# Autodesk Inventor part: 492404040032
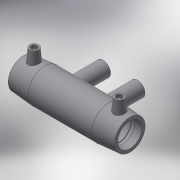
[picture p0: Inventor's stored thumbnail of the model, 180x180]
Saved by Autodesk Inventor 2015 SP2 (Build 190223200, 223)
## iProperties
Created: 2017-06
Part Number: 492404040032
Material: Generic
Description: PLASSON REDUCING TEE WITH TWO OUTLETS 40X32X32X40
Document SubType Name: Modeling
Designer: KIM
Mass: 57.3761 g
Surface Area: 241.06 cm^2
Volume: 57.3761 cm^3
Density: 1 g/cm^3
Appearance: Default
Author: KIM
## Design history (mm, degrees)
derived "492404.ipt"
feature "Solid1::492404.ipt"
tag "TaggingFeature1"
body "Solid1"
other parameters: "d0" = 176, "d2" = 56, "d3" = 46, "d4" = 35.2, "d5" = 50.4, "d6" = 38, "d8" = 168 deg, "d10" = 18.4, "d11" = 6.13333, "d23" = 56, "d29" = 46, "d30" = 15, "d31" = 70.4, "d34" = 5 deg, "d41" = 4, "d42" = 14, "d43" = 0, "d48" = -76, "d49" = 32, "d51" = 0, "d62" = 76, "d74" = -76, "d84" = 32, "d85" = 57, "d86" = 28.5, "d87" = 25.6, "d88" = 25.6, "d90" = 0, "d91" = 3, "d92" = 0, "L_" = 176, "L_1" = 46, "D_" = 56, "A_" = 46, "d_2" = 12, "H_" = 76, "L_2" = 57, "d_1" = 32
